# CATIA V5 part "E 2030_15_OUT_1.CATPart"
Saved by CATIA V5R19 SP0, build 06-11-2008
Material "Plastic": density 1200 kg/m3, Young's modulus 2.2e+09 Pa, Poisson ratio 0.38, thermal expansion 6.84e-05 1/K
Bounding box of the stored display mesh (mm): x -7.55 to 7.55, y -7.54 to 7.54, z -2 to 0
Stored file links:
  G:\UTB\Kombinované\Bakalářská práce\Catia\FORMA\E 2030_15_OUT_1.CATPart
  D:\Aplikace\CATIA\Nová složka\win_b64\startup\materials\Catalog.CATMaterial
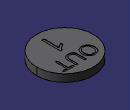
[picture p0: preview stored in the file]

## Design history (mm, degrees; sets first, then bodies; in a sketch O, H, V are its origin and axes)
Body1 "E 2030_15_OUT_1-8" (main body)
  Solid1: solid without history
